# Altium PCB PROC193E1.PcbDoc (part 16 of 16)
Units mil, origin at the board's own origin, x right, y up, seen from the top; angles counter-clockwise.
Board outline 7700 x 2300 mil, 6 copper layers (Top Layer, GND 1, SIG 1, PWR, GND 2, Bottom Layer), stack 60.98 mil thick; 946 components, 667 nets, 9401 pads, 1730 vias.
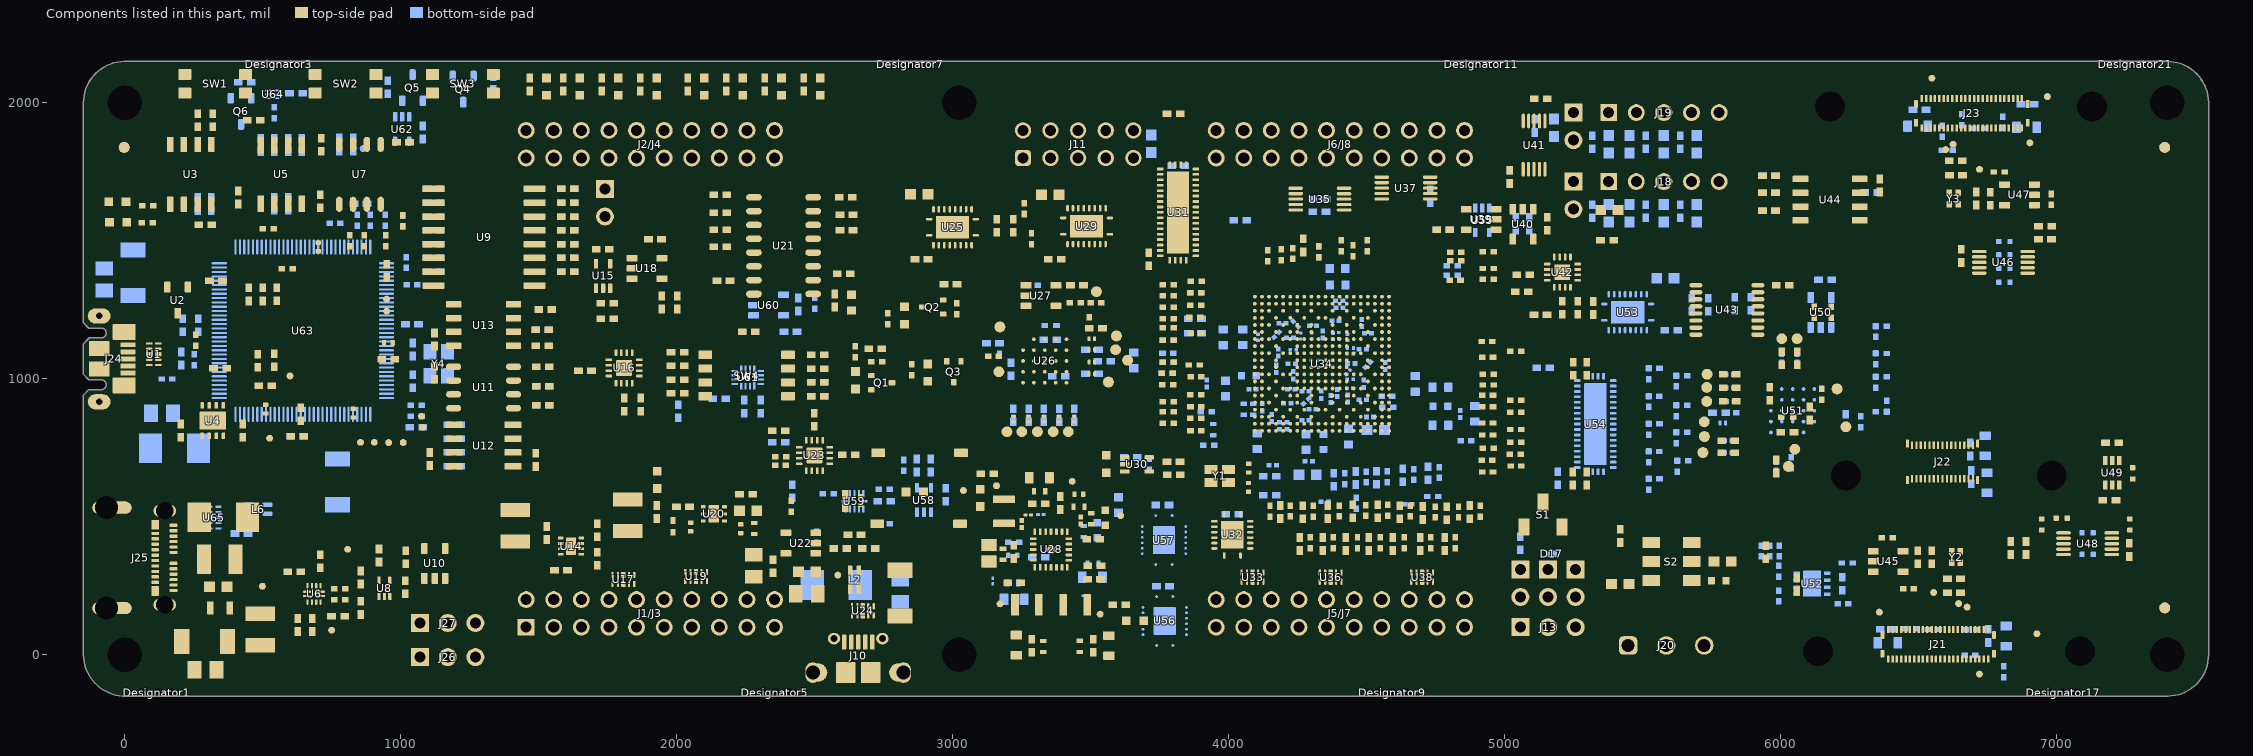
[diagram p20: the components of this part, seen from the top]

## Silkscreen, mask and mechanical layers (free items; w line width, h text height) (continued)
M10 Fab Notes:
  drawing of 220 lines, arcs and shapes, not listed
  text "SL#" at 7720,7515.45 h100
  text "LAYER" at 10020,7500 h100
  text "WIDTH(Mils)" at 10500,7500 h100
  text "SPACE(Mils)" at 11280,7500 h100
  text "IMPEDANCE(Ohms)" at 12100,7500 h100
  text "REF LAYER" at 13380,7500 h100
  text "TYPE" at 9060,7480 h100
  text "50" at 12700,7274.09 h100
  text "L02,L05" at 13509.77,7274.09 h100
  text "L1,L6" at 10121.22,7270.32 h100
  text "01" at 7760,7265.45 h100
  text "MICROSTRIP" at 8027.59,7260 h100
  text "5.3" at 10860,7260 h100
  text "NA" at 11680,7260 h100
  text "L02,L05" at 13510.44,7104.6 h100
  text "02" at 7760.19,7103.78 h100
  text "EDGE COUPLED MICROSTRIP" at 8029.1,7099.74 h100
  text "4.2" at 10860,7100 h100
  text "5" at 11760,7100 h100
  text "90" at 12700,7100 h100
  text "L1,L6" at 10121.22,7095.32 h100
  text "03" at 7760.19,6928.78 h100
  text "EDGE COUPLED MICROSTRIP" at 8029.1,6916.36 h100
  text "L05" at 13509.77,6915.09 h100
  text "L6" at 10121.22,6911.32 h100
  text "3.8" at 10896.99,6907.45 h100
  text "15" at 11700,6906 h100
  text "120" at 12641,6906 h100
  text "04" at 7760.19,6753.78 h100
  text "STRIPLINE" at 8023.97,6748.99 h100
  text "L3" at 10125.27,6741.99 h100
  text "L02/04" at 13510.44,6741 h100
  text "4.75" at 10896.99,6732.45 h100
  text "NA" at 11720,6726 h100
  text "50" at 12720,6726 h100
  text "05" at 7760.19,6578.78 h100
  text "L3" at 10128.27,6565.99 h100
  text "6" at 11760,6566 h100
  text "EDGE COUPLED STRIPLINE" at 8037.65,6560.7 h100
  text "90" at 12723.7,6561 h100
  text "L02/04" at 13510.44,6561 h100
  text "4" at 10899.99,6556.45 h100
  text "06" at 7760.19,6403.78 h100
  text "DESIGN INFORMATION" at 12232.02,6206.17 h60
  text "IMPEDANCE SPECIFICATIONS" at 8775,6160 h100
  text "3.8" at 12631.38,6077.2 h60
  text "MIN. TRACK WIDTH:" at 11587.46,6074.05 h60
  text "MIL" at 12838.46,6074.05 h60
  text "MIN. CLEARANCE:" at 11587.46,5949.92 h60
  text "4" at 12683.7,5949.92 h60
  text "MIL" at 12838.46,5949.92 h60
  text "MIN. VIA PAD SIZE:" at 11587.46,5825.8 h60
  text "18" at 12653.71,5825.8 h60
  text "MIL" at 12838.46,5825.8 h60
  text "0.05mm (2MIL)" at 12282.46,5695.9 h60
  text "MINIMUM ANNULAR RING" at 11258.23,5687.67 h60
  text "EXTERNAL" at 12990.46,5687.67 h60
  text "PER" at 11458.23,5577.55 h60
  text "IPC-D-275 CLASS 2 LEVEL C" at 11678.23,5577.54 h60
  text "MIL, HOLES" at 13166.46,5477.07 h60
  text "+/-" at 12774,5468.48 h60
  text "+/-" at 13628,5468.48 h60
  text "REGISTRATION TOLERANCES:" at 11258.23,5467.42 h60
  text "METAL" at 12458,5467.42 h60
  text "5" at 13034.2,5467.42 h60
  text "3" at 13867.2,5467.42 h60
  text "MIL" at 13983.46,5467.42 h60
  text "HOLE SIZE TOLERANCE (UNLESS OTHERWISE SPECIFIED):" at 11258.23,5369.1 h60
  text "+/-" at 13628,5366.23 h60
  text "3" at 13867.2,5365.17 h60
  text "MIL" at 13983.46,5365.17 h60
  text "MATERIAL:" at 11183.46,5227.52 h60
  text "FR-4 High Tg" at 12169.9,5099 h60
  text "X" at 12025.46,5091.01 h60
  text "FR-408" at 11604.46,5086.49 h60
  text "OTHER" at 13092.46,5086.49 h60
  text "LAYER STACK UP TABLE" at 8355,5020 h100
  text "62 MIL (1.6mm) +/-10%" at 11924.56,4943.46 h60
  text "X" at 11804.46,4941.01 h60
  text "THICKNESS:" at 11258.23,4935.24 h60
  text "OTHER" at 13209.46,4935.24 h60
  text "TOLERANCE:" at 11258.23,4796.92 h60
  text "X" at 12106.46,4796.92 h60
  text "ANSI IPC-6012 TYPE 3 CLASS 2" at 12284.48,4796.92 h60
  text "OTHER +/-" at 12284.46,4652.73 h60
  text "BOW & TWIST:" at 11258.23,4507.54 h60
  text "X" at 12106.46,4507.54 h60
  text "ANSI IPC-6012 TYPE 3 CLASS 2" at 12284.48,4507.54 h60
  text "OTHER +/-" at 12284.46,4360.85 h60
  text "DRILLING:" at 11183.46,4230.23 h60
  text "NC_DRILL FILES" at 12944.46,4125.04 h60
  text "REFERENCE:" at 11258.23,4121.1 h60
  text "X" at 11915.46,4121.01 h60
  text "AS SHOWN" at 12093.46,4121.1 h60
  text "X" at 12816.46,4121.1 h60
  text "OTHER" at 13242.46,3978.85 h60
  text "PTH COPPER THICKNESS:" at 11257.91,3975.32 h60
  text "X" at 12397.14,3975.32 h60
  text "20-30 um" at 12525.14,3975.32 h60
  text "BOARD FINISH:" at 11183.46,3827.73 h60
  text "SILKSCREEN:" at 11338.68,3717.6 h60
  text "X" at 12296.46,3717.6 h60
  text "TOP" at 12413.46,3717.6 h60
  text "X" at 12806.46,3717.6 h60
  text "BOTTOM" at 12924.46,3717.6 h60
  text "SILKSCREEN COLOR:" at 11338.68,3562.41 h60
  text "X" at 12295.46,3562.41 h60
  text "WHITE" at 12413.46,3562.41 h60
  text "OTHER" at 12924.46,3562.41 h60
  text "GREEN" at 12544.46,3418.96 h60
  text "X" at 13018.46,3418.96 h60
  text "OTHER" at 13162.46,3418.96 h60
  text "RED" at 13521.46,3418.96 h60
  text "SOLDER RESIST COLOR:" at 11338.68,3412.1 h60
  text "X" at 12426.46,3264.71 h60
  text "MATTE" at 12544.46,3264.71 h60
  text "SEMI-GLOSS" at 13162,3264.07 h60
  text "IMMERSION GOLD (ENIG)" at 12244.46,3091.94 h60
  text "ENEPIG" at 13582,3084.72 h60
  text "SURFACE FINISH:" at 11183.46,3083.72 h60
  text "X" at 12066.46,3083.72 h60
  text "IMM. TIN/SILVER OR EQUIV" at 11513,2946.4 h60
  text "OTHER" at 12944.46,2942.47 h60
  text "ARRAY/PANEL:" at 11183.46,2787.09 h60
  text "X" at 12066.46,2787.09 h60
  text "CUT AND TRIM PER M1 BOARD OUTLINE" at 12244.46,2778.87 h60
  text "N.C. ROUTE" at 12244.46,2642.9 h60
  text "V. SCORE" at 13110.46,2642.9 h60
  text "CERTIFICATION:" at 11183.46,2513.77 h60
  text "MATERIALS AND WORKMANSHIP FOR ALL PCBS" at 11908.46,2513.77 h60
  text "TO MEET OR EXCEED THE REQUIREMENTS OF:" at 11908.46,2419.71 h60
  text "X" at 11545.97,2291.08 h60
  text "ANSI IPC-A-600F CLASS ->" at 11673.96,2291.08 h60
  text "X" at 13321.97,2291.08 h60
  text "2" at 13431.96,2291.08 h60
  text "1" at 13116.96,2289.58 h60
  text "3" at 13785.96,2289.58 h60
  text "X" at 12357.97,2143.39 h60
  text "RoHS" at 12485.96,2143.39 h60
  text "OTHER" at 13130.36,2143.39 h60
  text "PER ORDER" at 13527.42,2143.39 h60
  text "ALL BOARDS MUST MEET OR EXCEED UL94-V0 REQUIREMENTS." at 11211,1989.57 h60
  text "PCB MUST BEAR THE UL94V-0 UL REGISTERED MATERIAL ID NUMBER" at 11211,1873.5 h60
  text "ADDITIONAL REQUIREMENTS:" at 11183.46,1704.08 h60
  text "MICROSECTION:" at 11258.23,1596.95 h60
  text "YES" at 12163.96,1596.95 h60
  text "REQUIRED" at 13025.46,1452.62 h60
  text "BARE BOARD ELEC. TEST:" at 11258.23,1449.76 h60
  text "NONE" at 12563.96,1449.76 h60
  text "X" at 12907.46,1449.76 h60
  text "PER ORDER" at 13617.46,1449.76 h60
  text "XX MIL VIAS REQUIRE NON-CONDUCTIVE FILL AND PLANARIZE" at 11362.99,1273.56 h59
  text "XX MIL VIAS REQUIRE CONDUCTIVE FILL AND PLANARIZE" at 11370.99,1169.58 h60
  text "OUTER XX MIL TRACES REQUIRE 50 OHM SINGLE-ENDED IMPEDANCE" at 11370,1006.2 h58
  text "LAYER 2 & 3 (INNER LAYERS) XX MIL WIDE, XX MIL SPACE / TRACES REQUIRE 100 OHM DIFFERENTIAL IMPEDANCE" at 11362,770.48 h60
  text ".Layer_Name" at 427,-1008.49 h60
M11 Gerber Information:
  lines w10: -442,-1080.17 6158,-1080.17 ; -442,-876.83 6160,-876.83 ; -442,-673.5 -442,-1283.5 3563,-1283.5 6160,-1283.5 6160,-673.5 -441.5,-673.5 -441.5,-1283.5 1134,-1283.5 ; 2023,-1283.5 2023,-673.5 ; 3290,-876.83 3290,-673.5 ; 4130,-876.83 4130,-673.5 ; 4752,-1290 4752,-1087.17
  text "ALL ARTWORK VIEWED FROM TOP SIDE" at -378.5,-805.67 h60
  text "BOARD #:" at 2098,-805.67 h60
  text ".PRJ_Number" at 2643.5,-805.67 h60
  text "REV:" at 3488,-805.67 h60
  text ".PCB_Rev" at 3779.5,-805.67 h60
  text "SVN REV:" at 4326,-805.67 h60
  text ".VersionControl_RevNumber" at 4832,-805.67 h60
  text "LAYER NAME =" at -378.5,-1008.49 h60
  text "TID #:" at 2098,-1009 h60
  text ".TID" at 2643.5,-1009 h60
  text "PLOT NAME =" at -378.5,-1214.34 h60
  text ".plot_File_Name" at 427,-1214.34 h60
  text "GENERATED    :" at 2100,-1214.34 h60
  text ".Print_Date" at 2969.5,-1214.34 h60
  text ".Print_Time" at 3698.5,-1214.34 h60
  text "TEXAS INSTRUMENTS" at 4963,-1214.34 h60
M12 Stackup:
  drawing of 332 lines, arcs and shapes, not listed
  text "Layer" at 8208.5,4798.43 h60
  text "Name" at 8459.6,4798.43 h60
  text "Material" at 8945.17,4798.43 h60
  text "Thickness" at 9842.95,4798.43 h60
  text "Constant" at 10201.38,4798.43 h60
  text "Board Layer Stack" at 10533.11,4798.43 h60
  text "Top Overlay" at 8459.6,4678.43 h60
  text "Top Solder" at 8459.6,4558.43 h60
  text "ELECTRA EMP 110/5410- RED" at 8945.17,4558.43 h60
  text "1.00mil" at 9842.95,4558.43 h60
  text "4" at 10201.38,4558.43 h60
  text "1" at 8208.5,4438.43 h60
  text "Top Layer" at 8459.6,4438.43 h60
  text "Copper Foil 18 microns" at 8945.17,4438.43 h60
  text "1.85mil" at 9842.95,4438.43 h60
  text "Dielectric 1" at 8459.6,4318.43 h60
  text "Iteq IT180A Prepreg 2113 RC58" at 8945.17,4318.43 h60
  text "3.55mil" at 9842.95,4318.43 h60
  text "4.13" at 10201.38,4318.43 h60
  text "2" at 8208.45,4198.43 h60
  text "GND 1" at 8459.6,4198.43 h60
  text "1.26mil" at 9842.95,4198.43 h60
  text "Dielectric 3" at 8459.6,4078.43 h60
  text "Iteq IT180A 4 mil core 1/1" at 8945.17,4078.43 h60
  text "4.00mil" at 9842.95,4078.43 h60
  text "4.4" at 10201.38,4078.43 h60
  text "3" at 8208.5,3958.43 h60
  text "SIG 1" at 8459.6,3958.43 h60
  text "1.26mil" at 9842.95,3958.43 h60
  text "Dielectric 5" at 8459.6,3838.43 h60
  text "Iteq IT180A Prepreg 106 RC71.5" at 8945.17,3838.43 h60
  text "1.86mil" at 9842.95,3838.43 h60
  text "3.79" at 10201.38,3838.43 h60
  text "Dielectric 7" at 8459.6,3718.43 h60
  text "Iteq IT180A Prepreg 1080 RC65" at 8945.17,3718.43 h60
  text "2.71mil" at 9842.9,3718.43 h60
  text "3.86" at 10201.38,3718.43 h60
  text "Dielectric1" at 8459.6,3598.43 h60
  text "Iteq IT180A 28 mil core H/H" at 8945.17,3598.43 h60
  text "28.00mil" at 9842.9,3598.43 h60
  text "4.53" at 10201.38,3598.43 h60
  text "Dielectric 8" at 8459.6,3478.43 h60
  text "Iteq IT180A Prepreg 1080 RC65" at 8945.17,3478.43 h60
  text "2.71mil" at 9842.9,3478.43 h60
  text "3.86" at 10201.38,3478.43 h60
  text "Dielectric 6" at 8459.6,3358.43 h60
  text "Iteq IT180A Prepreg 106 RC71.5" at 8945.17,3358.43 h60
  text "1.86mil" at 9842.95,3358.43 h60
  text "3.79" at 10201.38,3358.43 h60
  text "4" at 8208.5,3238.43 h60
  text "PWR" at 8459.6,3238.43 h60
  text "1.26mil" at 9842.95,3238.43 h60
  text "Dielectric 4" at 8459.6,3118.43 h60
  text "Iteq IT180A 4 mil core 1/1" at 8945.17,3118.43 h60
  text "4.00mil" at 9842.95,3118.43 h60
  text "4.4" at 10201.38,3118.43 h60
  text "5" at 8208.5,2998.43 h60
  text "GND 2" at 8459.6,2998.43 h60
  text "1.26mil" at 9842.95,2998.43 h60
  text "Dielectric 2" at 8459.6,2878.43 h60
  text "Iteq IT180A Prepreg 2113 RC58" at 8945.17,2878.43 h60
  text "3.55mil" at 9842.95,2878.43 h60
  text "4.13" at 10201.38,2878.43 h60
  text "6" at 8208.5,2758.43 h60
  text "Bottom Layer" at 8459.6,2758.43 h60
  text "Copper Foil 18 microns" at 8945.17,2758.43 h60
  text "1.85mil" at 9842.95,2758.43 h60
  text "Bottom Solder" at 8459.6,2638.43 h60
  text "ELECTRA EMP 110/5410- RED" at 8945.17,2638.43 h60
  text "1.00mil" at 9842.95,2638.43 h60
  text "4" at 10201.38,2638.43 h60
  text "Bottom Overlay" at 8459.6,2518.43 h60
  text ".Layer_Name" at 427,-1008.49 h60
M13 Component Bodies Top:
  text ".Layer_Name" at 427,-1008.49 h60
M14 Component Bodies Bottom:
  text ".Layer_Name" at 427,-1008.49 h60
M15 Courtyards Top:
  text ".Layer_Name" at 427,-1008.49 h60
M16 Courtyards Bottom:
  text ".Layer_Name" at 427,-1008.49 h60
Drill Drawing:
  drawing of 154 lines, arcs and shapes, not listed
  text "Symbol" at 157.75,7564.18 h65.8
  text "Quantity" at 622.83,7564.18 h65.8
  text "Finished Hole Size" at 1218.42,7564.18 h65.8
  text "Hole Length" at 2450.91,7564.18 h65.8
  text "Plated" at 3457.62,7564.18 h65.8
  text "Hole Tolerance (+)" at 3922.7,7564.18 h65.8
  text "Hole Tolerance (-)" at 5144.23,7564.18 h65.8
  text "1722" at 622.83,7427.1 h54.83
  text "8.00mil (0.203mm)" at 1218.42,7427.1 h54.83
  text "-" at 2450.91,7427.1 h54.83
  text "PTH" at 3457.62,7427.1 h54.83
  text "3.00mil (0.076mm)" at 3922.7,7427.1 h54.83
  text "3.00mil (0.076mm)" at 5144.23,7427.1 h54.83
  text "8" at 622.83,7290.01 h54.83
  text "11.81mil (0.300mm)" at 1218.42,7290.01 h54.83
  text "-" at 2450.91,7290.01 h54.83
  text "PTH" at 3457.62,7290.01 h54.83
  text "3.00mil (0.076mm)" at 3922.7,7290.01 h54.83
  text "3.00mil (0.076mm)" at 5144.23,7290.01 h54.83
  text "B" at 130.58,7280.02 h60.93
  text "2" at 622.83,7152.93 h54.83
  text "23.62mil (0.600mm)" at 1218.42,7152.93 h54.83
  text "51.18mil (1.300mm)" at 2450.91,7152.93 h54.83
  text "PTH" at 3457.62,7152.93 h54.83
  text "3.00mil (0.076mm)" at 3922.7,7152.93 h54.83
  text "3.00mil (0.076mm)" at 5144.23,7152.93 h54.83
  text "2" at 622.83,7015.84 h54.83
  text "25.59mil (0.650mm)" at 1218.42,7015.84 h54.83
  text "29.53mil (0.750mm)" at 2450.91,7015.84 h54.83
  text "PTH" at 3457.62,7015.84 h54.83
  text "3.00mil (0.076mm)" at 3922.7,7015.84 h54.83
  text "3.00mil (0.076mm)" at 5144.23,7015.84 h54.83
  text "48" at 622.83,6878.76 h54.83
  text "32.00mil (0.813mm)" at 1218.42,6878.76 h54.83
  text "-" at 2450.91,6878.76 h54.83
  text "NPTH" at 3457.62,6878.76 h54.83
  text "3.00mil (0.076mm)" at 3922.7,6878.76 h54.83
  text "3.00mil (0.076mm)" at 5144.23,6878.76 h54.83
  text "10" at 622.83,6741.68 h54.83
  text "39.37mil (1.000mm)" at 1218.42,6741.68 h54.83
  text "-" at 2450.91,6741.68 h54.83
  text "PTH" at 3457.62,6741.68 h54.83
  text "3.00mil (0.076mm)" at 3922.7,6741.68 h54.83
  text "3.00mil (0.076mm)" at 5144.23,6741.68 h54.83
  text "31" at 622.83,6604.59 h54.83
  text "40.00mil (1.016mm)" at 1218.42,6604.59 h54.83
  text "-" at 2450.91,6604.59 h54.83
  text "PTH" at 3457.62,6604.59 h54.83
  text "3.00mil (0.076mm)" at 3922.7,6604.59 h54.83
  text "3.00mil (0.076mm)" at 5144.23,6604.59 h54.83
  text "80" at 622.83,6467.51 h54.83
  text "40.16mil (1.020mm)" at 1218.42,6467.51 h54.83
  text "-" at 2450.91,6467.51 h54.83
  text "PTH" at 3457.62,6467.51 h54.83
  text "3.00mil (0.076mm)" at 3922.7,6467.51 h54.83
  text "3.00mil (0.076mm)" at 5144.23,6467.51 h54.83
  text "3" at 622.83,6330.42 h54.83
  text "47.24mil (1.200mm)" at 1218.42,6330.42 h54.83
  text "-" at 2450.91,6330.42 h54.83
  text "PTH" at 3457.62,6330.42 h54.83
  text "3.00mil (0.076mm)" at 3922.7,6330.42 h54.83
  text "3.00mil (0.076mm)" at 5144.23,6330.42 h54.83
  text "2" at 622.83,6193.34 h54.83
  text "51.18mil (1.300mm)" at 1218.42,6193.34 h54.83
  text "29.53mil (0.750mm)" at 2450.91,6193.34 h54.83
  text "PTH" at 3457.62,6193.34 h54.83
  text "3.00mil (0.076mm)" at 3922.7,6193.34 h54.83
  text "3.00mil (0.076mm)" at 5144.23,6193.34 h54.83
  text "2" at 622.83,6056.26 h54.83
  text "62.99mil (1.600mm)" at 1218.42,6056.26 h54.83
  text "23.62mil (0.600mm)" at 2450.91,6056.26 h54.83
  text "PTH" at 3457.62,6056.26 h54.83
  text "3.00mil (0.076mm)" at 3922.7,6056.26 h54.83
  text "3.00mil (0.076mm)" at 5144.23,6056.26 h54.83
  text "2" at 622.83,5919.17 h54.83
  text "82.68mil (2.100mm)" at 1218.42,5919.17 h54.83
  text "23.62mil (0.600mm)" at 2450.91,5919.17 h54.83
  text "PTH" at 3457.62,5919.17 h54.83
  text "3.00mil (0.076mm)" at 3922.7,5919.17 h54.83
  text "3.00mil (0.076mm)" at 5144.23,5919.17 h54.83
  text "6" at 622.83,5782.09 h54.83
  text "108.00mil (2.743mm)" at 1218.42,5782.09 h54.83
  text "-" at 2450.91,5782.09 h54.83
  text "NPTH" at 3457.62,5782.09 h54.83
  text "3.00mil (0.076mm)" at 3922.7,5782.09 h54.83
  text "3.00mil (0.076mm)" at 5144.23,5782.09 h54.83
  text "A" at 130.58,5772.1 h60.93
  text "10" at 622.83,5645 h54.83
  text "126.00mil (3.200mm)" at 1218.42,5645 h54.83
  text "-" at 2450.91,5645 h54.83
  text "NPTH" at 3457.62,5645 h54.83
  text "3.00mil (0.076mm)" at 3922.7,5645 h54.83
  text "3.00mil (0.076mm)" at 5144.23,5645 h54.83
  text "1928 Total" at 622.83,5507.92 h54.83
  text "Slot definitions :" at 157.75,5373.71 h54.83
  text "Routed Path Length" at 1103.93,5373.71 h54.83
  text "= Calculated from tool start centre position to tool end centre position." at 2114.06,5373.71 h54.83
  text "Hole Length" at 1103.93,5280.62 h54.83
  text "= Routed Path Length + Tool Size = Slot length as defined in the PCB layout" at 1739.49,5280.62 h54.83
  text ".Layer_Name" at 427,-1008.49 h60
M17 Embedded Cavity:
  text ".Layer_Name" at 427,-1008.49 h60
M18 Embedded Assembly:
  text ".Layer_Name" at 427,-1008.49 h60
M19 Embedded Keepout:
  text ".Layer_Name" at 427,-1008.49 h60
DXF_PROC193E1_TASY:
  drawing of 7140 lines, arcs and shapes, not listed
DXF_PROC193E1_BASY:
  drawing of 3808 lines, arcs and shapes, not listed
LP Logo:
  drawing of 8965 lines, arcs and shapes, not listed
  text "4" at 6389.42,574 h30
  text "6" at 6526.42,574 h30
  text "4" at 6048.42,485 h30
  text "6" at 5918.42,484 h30
  text "6" at 6105.42,483 h30
  text "4" at 5860.42,481 h30
  text "6" at 262.42,479 h30
  text "4" at 210.42,476 h30
  text "2" at 835.42,445 h30
  text "20" at 1746.42,442 h30
  text "3" at 6431.42,442 h30
  text "20" at 4245.42,438 h30
  text "2" at 3342.42,437 h30
  text "6" at 6510.42,423 h30
  text "4" at 6405.42,421 h30
  text "6" at -356.58,400 h30
  text "J2" at 1855.42,354 h30
  text "J6" at 4353.42,353 h30
  text "4" at -357.58,340 h30
  text "3" at 6049.42,340 h30
  text "3" at 5857.42,338 h30
  text "3" at -204.58,332 h30
  text "3" at 206.42,311 h30
  text "3" at 6429.42,286 h30
  text "5" at -70.58,274 h30
  text "4" at 5855.42,271 h30
  text "4" at 279.42,269 h30
  text "3" at 5717.42,269 h30
  text "B" at -423.58,251 h30
  text "J4" at 1852.42,242 h30
  text "J8" at 4350.42,241 h30
  text "6" at 5853.42,219 h30
  text "5" at 339.51,200.88 h30
  text "40" at -484.58,197 h30
  text "6" at 17.92,195 h30
  text "NOT FCC APPROVED FOR RESALE" at 6540.44,195.25 h50 r90
  text "20" at -260.58,189 h30 r270
  text "16" at 126.42,186 h30 r270
  text "19" at 1755.42,165 h30
  text "19" at 4248.42,162 h30
  text "8" at 339.51,140.88 h30
  text "FOR EVALUATION ONLY;" at 6440.49,140.27 h50 r90
  text "5" at 620.42,123 h30
  text "13" at 125.42,120 h30 r270
  text "16" at -221.58,112 h30
  text "A" at 1057.42,110 h30
  text "10" at 30.42,109 h30
  text "B" at 1362.42,90 h30
  text "13" at 4203.42,90 h30
  text "10" at 3127.42,89 h30
  text "12" at 3869.42,88 h30
  text "12" at 203.42,74 h30
  text "9" at 278.42,67 h30
  text "3" at 2326.42,63 h30
  text "5" at 4206.42,42 h30
  text "15" at -156.58,28 h30
  text "11" at -47.58,27 h30
  text "3" at 776.42,9 h30
  text "4" at 587.42,8 h30
  text "3" at 4360.42,-1 h30
  text "4" at 4209.92,-4 h30
  text "5" at 3341.09,-25.67 h30
  text "5" at 2173.42,-41 h30
  text "6" at 3120.42,-58 h30
  text "4" at 2323.42,-72 h30
  text "A" at 110.42,-112 h30
  text "97" at 57.42,-211 h30
  text "128" at 566.42,-211 h30
  text "24" at 4178.42,-231 h30
  text "6" at 4179.42,-301 h30
  text "5" at 4004.42,-305 h30
  text "16" at 5193.42,-307 h30
  text "5" at 4755.42,-341 h30
  text "4" at 4682.42,-343 h30
  text "3" at 5625.42,-356 h30
  text "4" at 5754.42,-366 h30
  text "WHEN ACTUATOR IS OPENED" at -766.5,-369 h30 r270
  text "4" at -372.58,-372 h30
  text "6" at 5754.42,-416 h30
  text "3" at 817.42,-423 h30
  text "4" at 905.42,-426 h30
  text "3" at 5624.42,-466 h30
  text "4" at 5750.42,-478 h30
  text "TEST AUTOMATION" at -507.58,-488 h30 r270
  text "3" at -379.58,-494 h30
  text "3" at 4683.42,-532 h30
  text "6" at 5749.42,-536 h30
  text "5" at 905.42,-548 h30
  text "2" at -250.58,-554 h30
  text "39" at 3425.42,-608 h30 r270
  text "42" at 3490.42,-608 h30 r270
  text "4" at 5757.42,-608 h30
  text "C" at 2246.42,-609 h30
  text "3" at 5615.42,-612 h30
  text "9" at 5183.09,-650.67 h30
  text "6" at 5754.42,-659 h30
  text "38" at 3374.42,-660 h30
  text "6" at -310.58,-662 h30
  text "8" at 5444.42,-693 h30
  text "6" at 4177.42,-729 h30
  text "5" at 4000.42,-730 h30
  text "3" at 5457.42,-738 h30
  text "4" at 5591.42,-739 h30
  text "4" at -324.58,-755 h30
  text "3" at -559.58,-777 h30
  text "6" at 5591.42,-793 h30
  text "4" at -400.58,-814 h30
  text "65" at -56.58,-818 h30
  text "32" at 666.42,-822 h30
  text "3" at 5458.42,-853 h30
  text "4" at 5592.42,-855 h30
  text "5" at -402.58,-894 h30
  text "6" at 5590.42,-906 h30
  text "64" at 56.42,-932 h30
  text "33" at 549.42,-936 h30
  text "4" at -74.58,-942 h30
  text "22" at 3379.42,-974 h30
  text "C" at 1061.42,-1036 h30
  text "www.ti.com/launchpad" at 3179.42,-1039 h30 r90
  text "21" at 3426.42,-1052 h30 r270
  text "18" at 3493.42,-1057 h30 r270
  text "3" at -124.58,-1058 h30
  text "2" at 1.42,-1061 h30
  text "5" at 4778.42,-1103 h30
  text "8" at 1823.42,-1112 h30
  text "4" at 4701.42,-1112 h30
  text "16" at 677.42,-1124 h30
  text "9" at 478.42,-1127 h30
  text "4" at 5773.42,-1144 h30
  text "5" at 1814.42,-1217 h30
  text "4" at 1922.42,-1233 h30
  text "2" at 830.42,-1254 h30
  text "20" at 4262.42,-1256 h30
  text "2" at 3332.42,-1257 h30
  text "20" at 1743.42,-1258 h30
  text "8" at 5625.42,-1276 h30
  text "Development Kit" at 2899.42,-1286 h30 r90
  text "LP-AM243" at 2848.42,-1288 h30 r90
  text "3" at 4701.42,-1306 h30
  text "5" at 5735.42,-1324 h30 r270
  text "J7" at 4351.42,-1342 h30
  text "J3" at 1847.42,-1344 h30
  text "7" at 4754.42,-1389 h30
  text "10" at 4990.42,-1391 h30
  text "J5" at 4348.42,-1454 h30
  text "J1" at 1844.42,-1456 h30
  text "8" at 473.42,-1465 h30
  text "2" at 4763.42,-1485 h30
  text "19" at 1722.42,-1537 h30
  text "19" at 4254.42,-1538 h30
  text "4" at 1714.42,-1626 h30
  text "3" at 1881.42,-1626 h30
DXF_PROC167A_TASY:
  drawing of 1198 lines, arcs and shapes, not listed
  text "BOTTOM ASSEMBLY OF PROC167A" at 5681.91,3615.16 h70
  text "BOTTOM ASSEMBLY OF PROC167A" at 7555.93,-1613.52 h70 r180

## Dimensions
-130.32,1183.41 to -150,1999.99 on M2 Board Dimensions
-120.32,960.97 to -140,0 on M2 Board Dimensions
-84.25,1166.5 to -84.25,1253.3 on M2 Board Dimensions
-150,-427.94 to 7550,-427.94 on M2 Board Dimensions
7418.82,2150.26 to 7400,-149.99 on M2 Board Dimensions
7550,5089 to 7550,-427.94 on M2 Board Dimensions
10072.36,-496.24 to 11072.36,-496.24 on M2 Board Dimensions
